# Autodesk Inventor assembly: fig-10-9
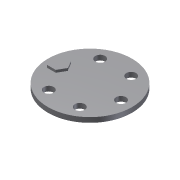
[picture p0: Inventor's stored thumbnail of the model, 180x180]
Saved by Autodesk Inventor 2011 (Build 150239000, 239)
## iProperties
Created: 2008-05
Part Number: fig-10-9
Document SubType Name: Assembly
Designer: CADCIM
Author: CADCIM
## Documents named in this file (3)
- C:\Users\CADSoft\Desktop\part files\c10-inv-2011-prt\fig-10-9.iam
- C:\Users\CADSoft\Desktop\inventor\c10-inv-2010-prt\c10\Part4.ipt
- C:\Users\CADSoft\Desktop\inventor\c10-inv-2010-prt\c10\Part5.ipt
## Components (2 placed, 2 different names)
1. Part4:1
2. Part5:1
